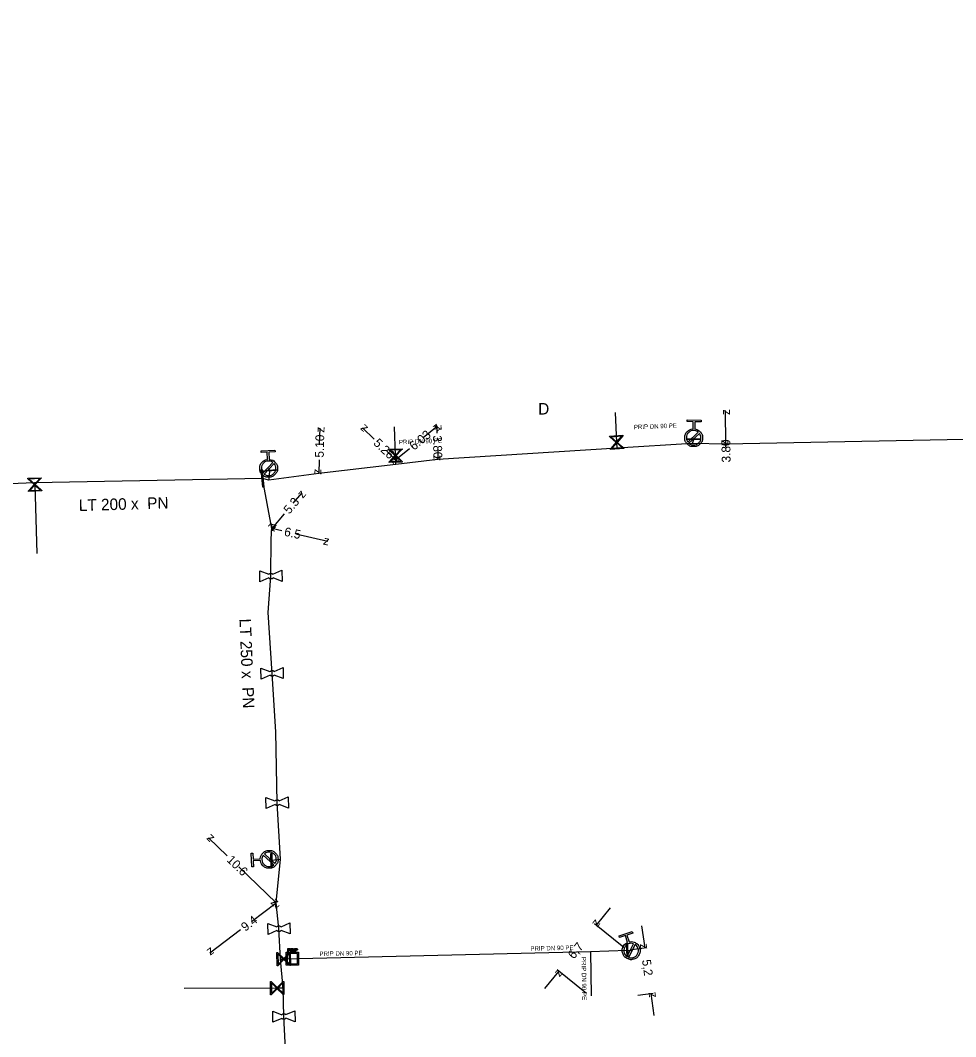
# Model space of a CAD drawing. Extents: x -643544 to -637295, y -1119190 to -1111715.
# Drawn here: x -641739.6 to -641634, y -1114373.2 to -1114258.4 of the extents above; entities that cross this region are included whole.
import ezdxf

# ---------------------------------------------------------------- set-up
doc = ezdxf.new("R2010")
doc.units = 0
for name, color, linetype in [('Default', 7, 'Continuous'), ('VP Hydrant', 7, 'Continuous'), ('VP Kótování', 7, 'Continuous'), ('VP Lomový bod', 7, 'Continuous'), ('VP Popis přípojky', 7, 'Continuous'), ('VP Přípojka', 7, 'Continuous'), ('VP Řad', 7, 'Continuous'), ('VP Řad - označení', 7, 'Continuous'), ('VP Řad - popis', 7, 'Continuous'), ('VP Šachta', 7, 'Continuous'), ('VP Šoupě', 7, 'Continuous')]:
    doc.layers.add(name, color=color, linetype=linetype)

msp = doc.modelspace()

# ---------------------------------------------------------------- linework, layer by layer
at = {"layer": 'Default'}
for points in [[(-641663.44, -1114304.55), (-641663.08, -1114304.59), (-641662.83, -1114304.86), (-641662.55, -1114305.16), (-641662.56, -1114305.57), (-641662.57, -1114305.99), (-641662.87, -1114306.27), (-641663.17, -1114306.56), (-641663.59, -1114306.54), (-641664, -1114306.53), (-641664.29, -1114306.23), (-641664.57, -1114305.93), (-641664.56, -1114305.52), (-641664.55, -1114305.1), (-641664.25, -1114304.82), (-641663.99, -1114304.56), (-641663.63, -1114304.55)], [(-641663.04, -1114304.92), (-641663.25, -1114304.74), (-641663.54, -1114304.73), (-641663.88, -1114304.72), (-641664.12, -1114304.95), (-641664.37, -1114305.18), (-641664.38, -1114305.52), (-641664.38, -1114305.81), (-641664.21, -1114306.04)], [(-641664.09, -1114306.17), (-641663.87, -1114306.35), (-641663.59, -1114306.36), (-641663.25, -1114306.36), (-641663, -1114306.13), (-641662.76, -1114305.9), (-641662.75, -1114305.57), (-641662.74, -1114305.28), (-641662.91, -1114305.06)], [(-641711.52, -1114307.99), (-641711.16, -1114308.01), (-641710.89, -1114308.26), (-641710.59, -1114308.54), (-641710.58, -1114308.96), (-641710.57, -1114309.37), (-641710.85, -1114309.67), (-641711.13, -1114309.97), (-641711.55, -1114309.99), (-641711.96, -1114310), (-641712.26, -1114309.72), (-641712.57, -1114309.43), (-641712.58, -1114309.02), (-641712.59, -1114308.6), (-641712.31, -1114308.3), (-641712.06, -1114308.03), (-641711.7, -1114307.99)], [(-641711.09, -1114308.34), (-641711.31, -1114308.16), (-641711.61, -1114308.17), (-641711.94, -1114308.18), (-641712.17, -1114308.43), (-641712.4, -1114308.67), (-641712.39, -1114309.01), (-641712.38, -1114309.3), (-641712.2, -1114309.51)], [(-641712.07, -1114309.64), (-641711.85, -1114309.81), (-641711.56, -1114309.8), (-641711.22, -1114309.79), (-641710.99, -1114309.54), (-641710.76, -1114309.3), (-641710.77, -1114308.96), (-641710.78, -1114308.67), (-641710.96, -1114308.46)], [(-641711.56, -1114320.96), (-641711.53, -1114320.93), (-641711.48, -1114320.9), (-641711.41, -1114320.85), (-641711.33, -1114320.85), (-641711.24, -1114320.85), (-641711.17, -1114320.89), (-641711.12, -1114320.92), (-641711.09, -1114320.96)], [(-641711.08, -1114321.36), (-641711.11, -1114321.4), (-641711.16, -1114321.43), (-641711.23, -1114321.48), (-641711.31, -1114321.48), (-641711.4, -1114321.48), (-641711.47, -1114321.44), (-641711.52, -1114321.41), (-641711.55, -1114321.37)], [(-641711.43, -1114331.95), (-641711.39, -1114331.91), (-641711.35, -1114331.88), (-641711.27, -1114331.83), (-641711.19, -1114331.83), (-641711.11, -1114331.83), (-641711.04, -1114331.87), (-641710.99, -1114331.9), (-641710.95, -1114331.94)], [(-641710.94, -1114332.34), (-641710.98, -1114332.39), (-641711.02, -1114332.41), (-641711.1, -1114332.46), (-641711.18, -1114332.46), (-641711.26, -1114332.46), (-641711.34, -1114332.42), (-641711.38, -1114332.39), (-641711.42, -1114332.35)], [(-641710.86, -1114346.55), (-641710.83, -1114346.51), (-641710.78, -1114346.48), (-641710.7, -1114346.44), (-641710.62, -1114346.43), (-641710.54, -1114346.43), (-641710.47, -1114346.47), (-641710.42, -1114346.5), (-641710.38, -1114346.54)], [(-641710.38, -1114346.95), (-641710.41, -1114346.99), (-641710.46, -1114347.01), (-641710.53, -1114347.06), (-641710.61, -1114347.06), (-641710.69, -1114347.06), (-641710.77, -1114347.02), (-641710.82, -1114347), (-641710.85, -1114346.96)], [(-641712.52, -1114353.09), (-641712.5, -1114352.73), (-641712.25, -1114352.46), (-641711.97, -1114352.16), (-641711.56, -1114352.14), (-641711.14, -1114352.12), (-641710.84, -1114352.4), (-641710.54, -1114352.69), (-641710.52, -1114353.1), (-641710.5, -1114353.51), (-641710.78, -1114353.82), (-641711.06, -1114354.12), (-641711.48, -1114354.14), (-641711.89, -1114354.16), (-641712.2, -1114353.88), (-641712.47, -1114353.63), (-641712.51, -1114353.27)], [(-641712.18, -1114352.66), (-641712.34, -1114352.88), (-641712.33, -1114353.17), (-641712.32, -1114353.51), (-641712.07, -1114353.74), (-641711.82, -1114353.97), (-641711.49, -1114353.95), (-641711.19, -1114353.94), (-641710.99, -1114353.76)], [(-641710.86, -1114353.62), (-641710.7, -1114353.4), (-641710.71, -1114353.11), (-641710.72, -1114352.77), (-641710.97, -1114352.54), (-641711.22, -1114352.32), (-641711.55, -1114352.33), (-641711.84, -1114352.34), (-641712.05, -1114352.52)], [(-641710.65, -1114360.77), (-641710.62, -1114360.73), (-641710.58, -1114360.71), (-641710.5, -1114360.66), (-641710.42, -1114360.66), (-641710.34, -1114360.66), (-641710.26, -1114360.7), (-641710.21, -1114360.73), (-641710.18, -1114360.77)], [(-641710.17, -1114361.17), (-641710.2, -1114361.21), (-641710.25, -1114361.24), (-641710.32, -1114361.29), (-641710.41, -1114361.29), (-641710.49, -1114361.29), (-641710.56, -1114361.25), (-641710.61, -1114361.22), (-641710.65, -1114361.18)], [(-641709.27, -1114363.21), (-641709.24, -1114363.21), (-641709.22, -1114363.22), (-641709.19, -1114363.22), (-641709.18, -1114363.23), (-641709.16, -1114363.24), (-641709.15, -1114363.27), (-641709.14, -1114363.29), (-641709.14, -1114363.32), (-641709.14, -1114363.36), (-641709.17, -1114363.39), (-641709.19, -1114363.42), (-641709.27, -1114363.42)], [(-641709.27, -1114363.38), (-641709.22, -1114363.38), (-641709.2, -1114363.37), (-641709.19, -1114363.35), (-641709.19, -1114363.32), (-641709.19, -1114363.29), (-641709.2, -1114363.28), (-641709.21, -1114363.26), (-641709.23, -1114363.26), (-641709.24, -1114363.25), (-641709.27, -1114363.25)], [(-641708.94, -1114363.37), (-641708.91, -1114363.37), (-641708.89, -1114363.36), (-641708.87, -1114363.36), (-641708.86, -1114363.34), (-641708.85, -1114363.33), (-641708.85, -1114363.31), (-641708.85, -1114363.29), (-641708.87, -1114363.27), (-641708.89, -1114363.25), (-641708.93, -1114363.25)], [(-641708.93, -1114363.21), (-641708.88, -1114363.21), (-641708.86, -1114363.22), (-641708.83, -1114363.23), (-641708.82, -1114363.26), (-641708.8, -1114363.28), (-641708.8, -1114363.31), (-641708.8, -1114363.35), (-641708.83, -1114363.37), (-641708.85, -1114363.4), (-641708.9, -1114363.41), (-641708.89, -1114363.42), (-641708.88, -1114363.43), (-641708.85, -1114363.44), (-641708.84, -1114363.47)], [(-641708.47, -1114363.21), (-641708.44, -1114363.21), (-641708.42, -1114363.22), (-641708.39, -1114363.22), (-641708.37, -1114363.23), (-641708.36, -1114363.25), (-641708.35, -1114363.27), (-641708.33, -1114363.29), (-641708.33, -1114363.32), (-641708.33, -1114363.36), (-641708.36, -1114363.39), (-641708.39, -1114363.43), (-641708.47, -1114363.43)], [(-641708.47, -1114363.38), (-641708.42, -1114363.38), (-641708.4, -1114363.37), (-641708.38, -1114363.35), (-641708.38, -1114363.32), (-641708.38, -1114363.3), (-641708.39, -1114363.28), (-641708.41, -1114363.26), (-641708.42, -1114363.26), (-641708.44, -1114363.26), (-641708.47, -1114363.26)], [(-641670.85, -1114362.47), (-641670.49, -1114362.39), (-641670.17, -1114362.55), (-641669.8, -1114362.74), (-641669.67, -1114363.14), (-641669.54, -1114363.53), (-641669.73, -1114363.9), (-641669.92, -1114364.27), (-641670.31, -1114364.4), (-641670.7, -1114364.53), (-641671.07, -1114364.34), (-641671.44, -1114364.15), (-641671.57, -1114363.76), (-641671.7, -1114363.37), (-641671.52, -1114363), (-641671.35, -1114362.67), (-641671.02, -1114362.53)], [(-641670.34, -1114362.68), (-641670.6, -1114362.58), (-641670.88, -1114362.67), (-641671.2, -1114362.78), (-641671.35, -1114363.08), (-641671.5, -1114363.38), (-641671.4, -1114363.7), (-641671.31, -1114363.98), (-641671.07, -1114364.13)], [(-641670.91, -1114364.21), (-641670.65, -1114364.31), (-641670.37, -1114364.22), (-641670.05, -1114364.11), (-641669.9, -1114363.81), (-641669.75, -1114363.51), (-641669.85, -1114363.19), (-641669.94, -1114362.92), (-641670.18, -1114362.77)], [(-641708.88, -1114363.5), (-641708.9, -1114363.46), (-641708.91, -1114363.45), (-641708.93, -1114363.43), (-641708.94, -1114363.42), (-641708.95, -1114363.42), (-641708.96, -1114363.41), (-641708.97, -1114363.41), (-641708.99, -1114363.41)], [(-641710.1, -1114370.69), (-641710.07, -1114370.65), (-641710.02, -1114370.62), (-641709.95, -1114370.58), (-641709.87, -1114370.58), (-641709.79, -1114370.58), (-641709.71, -1114370.62), (-641709.66, -1114370.64), (-641709.63, -1114370.68)], [(-641709.62, -1114371.09), (-641709.65, -1114371.13), (-641709.7, -1114371.16), (-641709.77, -1114371.2), (-641709.85, -1114371.2), (-641709.94, -1114371.21), (-641710.01, -1114371.16), (-641710.06, -1114371.14), (-641710.09, -1114371.1)]]:
    msp.add_open_spline(points, degree=3, dxfattribs=at)
at = {"layer": 'VP Hydrant'}
for points in [[(-641663.63, -1114304.55), (-641663.6, -1114303.73), (-641664.29, -1114303.71), (-641664.29, -1114303.52), (-641662.72, -1114303.57), (-641662.73, -1114303.75), (-641663.42, -1114303.73), (-641663.44, -1114304.55)], [(-641664.21, -1114306.04), (-641663.04, -1114304.92)], [(-641662.91, -1114305.06), (-641664.09, -1114306.17)], [(-641711.7, -1114307.99), (-641711.73, -1114307.17), (-641712.42, -1114307.2), (-641712.42, -1114307.01), (-641710.86, -1114306.96), (-641710.85, -1114307.15), (-641711.54, -1114307.17), (-641711.52, -1114307.99)], [(-641712.2, -1114309.51), (-641711.09, -1114308.34)], [(-641710.96, -1114308.46), (-641712.07, -1114309.64)], [(-641712.51, -1114353.27), (-641713.33, -1114353.31), (-641713.3, -1114353.99), (-641713.49, -1114354), (-641713.55, -1114352.44), (-641713.37, -1114352.43), (-641713.34, -1114353.12), (-641712.52, -1114353.09)], [(-641710.99, -1114353.76), (-641712.18, -1114352.66)], [(-641712.05, -1114352.52), (-641710.86, -1114353.62)], [(-641671.02, -1114362.53), (-641671.28, -1114361.75), (-641671.93, -1114361.96), (-641671.99, -1114361.79), (-641670.5, -1114361.3), (-641670.45, -1114361.48), (-641671.1, -1114361.69), (-641670.85, -1114362.47)], [(-641671.07, -1114364.13), (-641670.34, -1114362.68)], [(-641670.18, -1114362.77), (-641670.91, -1114364.21)]]:
    msp.add_lwpolyline(points, dxfattribs=at)
at = {"layer": 'VP Kótování'}
for points in [[(-641659.92, -1114306.27), (-641659.97, -1114302.47)], [(-641705.82, -1114306.35), (-641705.77, -1114304.47)], [(-641699.65, -1114305.7), (-641700.98, -1114304.41)], [(-641694.13, -1114305.52), (-641692.54, -1114304.22)], [(-641692.53, -1114305.03), (-641692.55, -1114304.21)], [(-641698.24, -1114307.06), (-641697.2, -1114308.06)], [(-641695.67, -1114306.79), (-641697.21, -1114308.04)], [(-641692.47, -1114307), (-641692.45, -1114308.01)], [(-641659.91, -1114306.61), (-641659.92, -1114306.27)], [(-641705.86, -1114308.04), (-641705.91, -1114309.57)], [(-641708.79, -1114312.93), (-641707.78, -1114311.75)], [(-641709.81, -1114314.13), (-641711.22, -1114315.78)], [(-641710.07, -1114316.04), (-641711.22, -1114315.78)], [(-641708.51, -1114316.39), (-641704.88, -1114317.2)], [(-641716.26, -1114352.73), (-641718.36, -1114350.7)], [(-641714.95, -1114353.98), (-641710.73, -1114358.05)], [(-641713.51, -1114360.16), (-641710.73, -1114358.05)], [(-641673, -1114358.63), (-641674.57, -1114360.58)], [(-641671.46, -1114363.1), (-641674.77, -1114360.42)], [(-641669.44, -1114360.66), (-641669.09, -1114363.13)], [(-641714.77, -1114361.11), (-641718.22, -1114363.73)], [(-641670.57, -1114363.34), (-641668.84, -1114363.1)], [(-641675.67, -1114368.31), (-641678.98, -1114365.63)], [(-641680.36, -1114367.73), (-641678.78, -1114365.79)], [(-641669.85, -1114368.49), (-641668.13, -1114368.25)], [(-641668.03, -1114370.76), (-641668.37, -1114368.28)]]:
    msp.add_lwpolyline(points, dxfattribs=at)
at = {"layer": 'VP Lomový bod'}
for points in [[(-641712.56, -1114321.82), (-641712.58, -1114320.57), (-641711.56, -1114320.96)], [(-641711.09, -1114320.96), (-641710.08, -1114320.51), (-641710.06, -1114321.76), (-641711.08, -1114321.36)], [(-641711.55, -1114321.37), (-641712.56, -1114321.82)], [(-641712.42, -1114332.8), (-641712.45, -1114331.55), (-641711.43, -1114331.95)], [(-641711.42, -1114332.35), (-641712.42, -1114332.8)], [(-641710.95, -1114331.94), (-641709.95, -1114331.49), (-641709.92, -1114332.74), (-641710.94, -1114332.34)], [(-641711.85, -1114347.4), (-641711.88, -1114346.15), (-641710.86, -1114346.55)], [(-641710.38, -1114346.54), (-641709.38, -1114346.1), (-641709.35, -1114347.35), (-641710.38, -1114346.95)], [(-641710.85, -1114346.96), (-641711.85, -1114347.4)], [(-641711.65, -1114361.63), (-641711.68, -1114360.38), (-641710.65, -1114360.77)], [(-641710.18, -1114360.77), (-641709.18, -1114360.32), (-641709.15, -1114361.57), (-641710.17, -1114361.17)], [(-641710.65, -1114361.18), (-641711.65, -1114361.63)], [(-641709.63, -1114370.68), (-641708.62, -1114370.24), (-641708.6, -1114371.49), (-641709.62, -1114371.09)], [(-641711.1, -1114371.54), (-641711.12, -1114370.29), (-641710.1, -1114370.69)], [(-641710.09, -1114371.1), (-641711.1, -1114371.54)]]:
    msp.add_lwpolyline(points, dxfattribs=at)
at = {"layer": 'VP Přípojka'}
for points in [[(-641672.22, -1114306.72), (-641672.25, -1114306.07), (-641672.38, -1114302.68)], [(-641697.21, -1114308.56), (-641697.25, -1114307.56), (-641697.37, -1114304.3)], [(-641663.56, -1114305.54), (-641663.54, -1114305.69), (-641663.72, -1114306.18)], [(-641711.58, -1114308.99), (-641711.48, -1114309.25), (-641711.56, -1114310.32)], [(-641738.02, -1114310.65), (-641738, -1114310.83), (-641737.78, -1114318.6)], [(-641711.52, -1114353.14), (-641711.26, -1114353.23), (-641710.24, -1114353.14)], [(-641710.23, -1114364.42), (-641709.87, -1114364.4), (-641709.72, -1114364.39), (-641675.21, -1114363.54), (-641671.07, -1114363.41), (-641670.62, -1114363.45)], [(-641675.21, -1114363.54), (-641675.15, -1114368.57)], [(-641709.94, -1114367.68), (-641710.61, -1114367.68), (-641721.14, -1114367.72)]]:
    msp.add_lwpolyline(points, dxfattribs=at)
at = {"layer": 'VP Řad'}
for points in [[(-641712.28, -1114310.14), (-641738.02, -1114310.65), (-641747.38, -1114311), (-641751.05, -1114311.27), (-641752.55, -1114285.69), (-641752.72, -1114277.81), (-641752.84, -1114265.29), (-641753.28, -1114256.06), (-641753.76, -1114245.87), (-641744.6, -1114230.77)], [(-641592.04, -1114288.86), (-641594.82, -1114288.35), (-641595.28, -1114288.25), (-641595.44, -1114289.43), (-641597.14, -1114298.01), (-641596.97, -1114299.53), (-641598.14, -1114304.08), (-641605.54, -1114305.2), (-641616.32, -1114305.43), (-641627.23, -1114305.64), (-641659.92, -1114306.27), (-641663.72, -1114306.18), (-641672.22, -1114306.72), (-641692.45, -1114308.01), (-641697.21, -1114308.56), (-641705.91, -1114309.57), (-641711.56, -1114310.32), (-641712.28, -1114310.14)], [(-641709.34, -1114381.17), (-641709.86, -1114370.89), (-641709.94, -1114367.68), (-641710.23, -1114364.42), (-641710.41, -1114360.97), (-641710.73, -1114358.05), (-641710.24, -1114353.14), (-641710.62, -1114346.75), (-641710.75, -1114338.75), (-641711.18, -1114332.15), (-641711.65, -1114325.29), (-641711.32, -1114321.16), (-641711.31, -1114316.97), (-641711.22, -1114315.78), (-641712.28, -1114310.14)]]:
    msp.add_lwpolyline(points, dxfattribs=at)
at = {"layer": 'VP Šachta'}
for points in [[(-641709.41, -1114363.57), (-641709.41, -1114363.21), (-641709.27, -1114363.21)], [(-641709.27, -1114363.25), (-641709.36, -1114363.25), (-641709.36, -1114363.38)], [(-641709.36, -1114363.38), (-641709.27, -1114363.38)], [(-641709.09, -1114363.57), (-641709.09, -1114363.21), (-641708.93, -1114363.21)], [(-641708.93, -1114363.25), (-641709.04, -1114363.25), (-641709.04, -1114363.37)], [(-641709.04, -1114363.37), (-641708.94, -1114363.37)], [(-641708.73, -1114363.57), (-641708.73, -1114363.21), (-641708.68, -1114363.21), (-641708.68, -1114363.57), (-641708.73, -1114363.57)], [(-641708.61, -1114363.57), (-641708.61, -1114363.21), (-641708.47, -1114363.21)], [(-641708.47, -1114363.26), (-641708.56, -1114363.26), (-641708.56, -1114363.38)], [(-641708.56, -1114363.38), (-641708.47, -1114363.38)], [(-641708.19, -1114363.63), (-641708.19, -1114365.09), (-641709.6, -1114365.09), (-641709.6, -1114363.63), (-641708.19, -1114363.63)], [(-641709.48, -1114363.76), (-641709.48, -1114364.96), (-641708.31, -1114364.96), (-641708.31, -1114363.76), (-641709.48, -1114363.76)], [(-641709.27, -1114363.42), (-641709.36, -1114363.42), (-641709.36, -1114363.57), (-641709.41, -1114363.57)], [(-641708.99, -1114363.41), (-641709.04, -1114363.41), (-641709.04, -1114363.57), (-641709.09, -1114363.57)], [(-641708.84, -1114363.47), (-641708.77, -1114363.57), (-641708.83, -1114363.57), (-641708.88, -1114363.5)], [(-641708.47, -1114363.43), (-641708.56, -1114363.43), (-641708.56, -1114363.57), (-641708.61, -1114363.57)]]:
    msp.add_lwpolyline(points, dxfattribs=at)
at = {"layer": 'VP Šoupě'}
for points in [[(-641671.44, -1114306.76), (-641672.94, -1114306.88), (-641672.94, -1114306.81), (-641672.86, -1114306.72), (-641672.31, -1114306.08), (-641673.05, -1114305.45), (-641673.06, -1114305.38), (-641671.56, -1114305.26), (-641671.56, -1114305.33), (-641672.19, -1114306.07), (-641671.55, -1114306.61), (-641671.45, -1114306.69), (-641671.44, -1114306.76)], [(-641672.9, -1114305.46), (-641672.26, -1114306.01), (-641671.71, -1114305.37), (-641672.9, -1114305.46)], [(-641664.29, -1114305.63), (-641662.79, -1114305.65), (-641662.79, -1114305.74), (-641664.29, -1114305.73), (-641664.29, -1114305.63)], [(-641698.01, -1114306.82), (-641696.51, -1114306.79), (-641696.51, -1114306.86), (-641696.6, -1114306.95), (-641697.18, -1114307.55), (-641696.48, -1114308.22), (-641696.48, -1114308.29), (-641697.98, -1114308.32), (-641697.98, -1114308.26), (-641697.31, -1114307.56), (-641697.92, -1114306.98), (-641698.01, -1114306.89), (-641698.01, -1114306.82)], [(-641697.85, -1114306.91), (-641697.25, -1114307.49), (-641696.67, -1114306.89), (-641697.85, -1114306.91)], [(-641671.61, -1114306.68), (-641672.25, -1114306.13), (-641672.79, -1114306.77), (-641671.61, -1114306.68)], [(-641696.63, -1114308.2), (-641697.24, -1114307.62), (-641697.82, -1114308.23), (-641696.63, -1114308.2)], [(-641712.3, -1114309.13), (-641712.12, -1114311.13), (-641712.25, -1114311.14), (-641712.43, -1114309.15), (-641712.3, -1114309.13)], [(-641712.23, -1114309.26), (-641710.74, -1114309.13), (-641710.73, -1114309.23), (-641712.22, -1114309.36), (-641712.23, -1114309.26)], [(-641737.22, -1114311.55), (-641738.72, -1114311.61), (-641738.72, -1114311.55), (-641738.63, -1114311.45), (-641738.06, -1114310.83), (-641738.78, -1114310.18), (-641738.78, -1114310.11), (-641737.28, -1114310.05), (-641737.28, -1114310.11), (-641737.94, -1114310.83), (-641737.32, -1114311.4), (-641737.22, -1114311.48), (-641737.22, -1114311.55)], [(-641738.63, -1114310.2), (-641738, -1114310.77), (-641737.44, -1114310.15), (-641738.63, -1114310.2)], [(-641737.38, -1114311.46), (-641738, -1114310.89), (-641738.56, -1114311.51), (-641737.38, -1114311.46)], [(-641711.29, -1114353.98), (-641711.32, -1114352.48), (-641711.23, -1114352.48), (-641711.2, -1114353.98), (-641711.29, -1114353.98)], [(-641671.05, -1114362.66), (-641670.99, -1114364.16), (-641671.09, -1114364.16), (-641671.14, -1114362.66), (-641671.05, -1114362.66)], [(-641709.15, -1114363.62), (-641709.1, -1114365.12), (-641709.16, -1114365.12), (-641709.26, -1114365.03), (-641709.87, -1114364.46), (-641710.53, -1114365.17), (-641710.6, -1114365.17), (-641710.65, -1114363.67), (-641710.58, -1114363.67), (-641709.87, -1114364.33), (-641709.3, -1114363.72), (-641709.21, -1114363.62), (-641709.15, -1114363.62)], [(-641710.51, -1114365.01), (-641709.93, -1114364.4), (-641710.55, -1114363.82), (-641710.51, -1114365.01)], [(-641709.24, -1114363.78), (-641709.81, -1114364.39), (-641709.2, -1114364.97), (-641709.24, -1114363.78)], [(-641709.87, -1114366.92), (-641709.85, -1114368.42), (-641709.91, -1114368.42), (-641710, -1114368.33), (-641710.61, -1114367.75), (-641711.28, -1114368.44), (-641711.35, -1114368.44), (-641711.37, -1114366.94), (-641711.3, -1114366.94), (-641710.61, -1114367.62), (-641710.02, -1114367.02), (-641709.93, -1114366.92), (-641709.87, -1114366.92)], [(-641711.26, -1114368.29), (-641710.67, -1114367.68), (-641711.27, -1114367.1), (-641711.26, -1114368.29)], [(-641709.96, -1114367.08), (-641710.54, -1114367.68), (-641709.94, -1114368.27), (-641709.96, -1114367.08)]]:
    msp.add_lwpolyline(points, dxfattribs=at)

# ---------------------------------------------------------------- texts
at = {"layer": 'VP Kótování'}
for s, rotation, p in [('z', 90.7698, (-641659.46, -1114302.97)), ('z', 88.4944, (-641705.28, -1114304.98)), ('z', 136.0162, (-641700.28, -1114304.4)), ('6.03', 39.3469, (-641695.16, -1114307.02)), ('z', 39.3469, (-641692.61, -1114304.92)), ('z', 91.5384, (-641692.04, -1114304.7)), ('5.10', 88.4944, (-641705.36, -1114307.8)), ('5.26', 316.0161, (-641699.81, -1114306.23)), ('3.80', 271.5384, (-641693.02, -1114305.29)), ('3.80', 90.7698, (-641659.39, -1114308.33)), ('z', 270.7697, (-641660.42, -1114305.78)), ('z', 316.0162, (-641697.9, -1114308.08)), ('z', 219.3469, (-641697.14, -1114307.34)), ('z', 271.5384, (-641692.96, -1114307.52)), ('z', 268.4943, (-641706.39, -1114309.05)), ('z', 49.4926, (-641707.72, -1114312.45)), ('5.3', 49.4926, (-641709.24, -1114314.23)), ('z', 229.4925, (-641711.28, -1114315.07)), ('z', 167.3708, (-641710.62, -1114315.4)), ('6.5', 347.3708, (-641709.89, -1114316.59)), ('z', 347.3708, (-641705.48, -1114317.58)), ('z', 136.0703, (-641717.65, -1114350.69)), ('10.6', 316.0703, (-641716.39, -1114353.3)), ('z', 316.0702, (-641711.43, -1114358.07)), ('z', 37.1405, (-641710.82, -1114358.75)), ('9.4', 37.1405, (-641714.22, -1114361.33)), ('z', 231.0456, (-641674.65, -1114359.87)), ('z', 217.1405, (-641718.12, -1114363.03)), ('6,7', 51.0456, (-641677.09, -1114364.48)), ('z', 277.9333, (-641669.65, -1114362.71)), ('5,2', 277.9333, (-641669.4, -1114364.52)), ('z', 51.0456, (-641678.71, -1114366.49)), ('z', 97.9333, (-641667.81, -1114368.71))]:
    msp.add_text(s, height=1, rotation=rotation, dxfattribs=at).set_placement(p)
at = {"layer": 'VP Popis přípojky'}
for rotation, p in [(2.1995, (-641670.31, -1114304.59)), (2.1491, (-641696.85, -1114306.29)), (1.3363, (-641682, -1114363.47)), (1.3363, (-641705.83, -1114364.07)), (270.6267, (-641676.22, -1114364.17))]:
    msp.add_text('PRIP DN 90 PE', height=0.5, rotation=rotation, dxfattribs=at).set_placement(p)
at = {"layer": 'VP Řad - označení'}
msp.add_text('D', height=1.3, dxfattribs=at).set_placement((-641681.13, -1114302.92))
at = {"layer": 'VP Řad - popis'}
for s, rotation, p in [('LT 200 x  PN ', 1.6745, (-641733.01, -1114313.82)), ('LT 250 x  PN ', 272.3247, (-641714.88, -1114325.99))]:
    msp.add_text(s, height=1.3, rotation=rotation, dxfattribs=at).set_placement(p)

doc.saveas('drawing.dxf')
